// Mitsubishi GX Works2 project: 亮灯练习   PLC: FX3U/FX3UC

PROGRAM MAIN
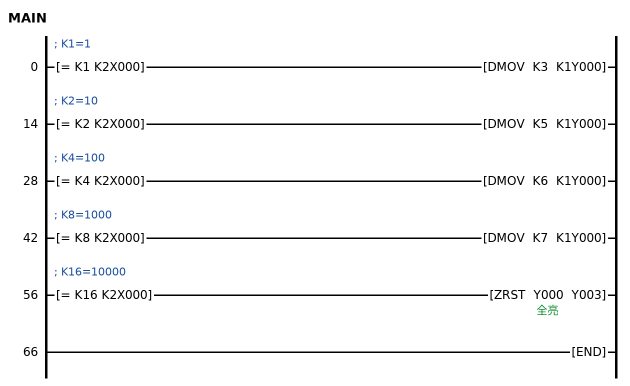
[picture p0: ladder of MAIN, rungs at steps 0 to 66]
; K1=1
0     LD=     K1 K2X000  ; 按钮
      DMOV    K3 K1Y000  ; 全亮
        [note] Y0,Y1亮
; K2=10
14    LD=     K2 K2X000  ; 按钮
      DMOV    K5 K1Y000
        [note] Y0,Y2亮
; K4=100
28    LD=     K4 K2X000  ; 按钮
      DMOV    K6 K1Y000
        [note] Y1,Y2亮
; K8=1000
42    LD=     K8 K2X000  ; 按钮
      DMOV    K7 K1Y000
        [note] Y0-Y2全亮
; K16=10000
56    LD=     K16 K2X000  ; 按钮
      ZRST    Y000 Y003
        [note] 全灭
66    END
END_PROGRAM

// device comments not shown above
Y001  ; 0,2亮
X001  ; 0,2亮
X002  ; 全亮
X003  ; 1,2亮
X004  ; 全灭
M0  ; 停止标志
